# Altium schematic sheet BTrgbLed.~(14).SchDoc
size A4
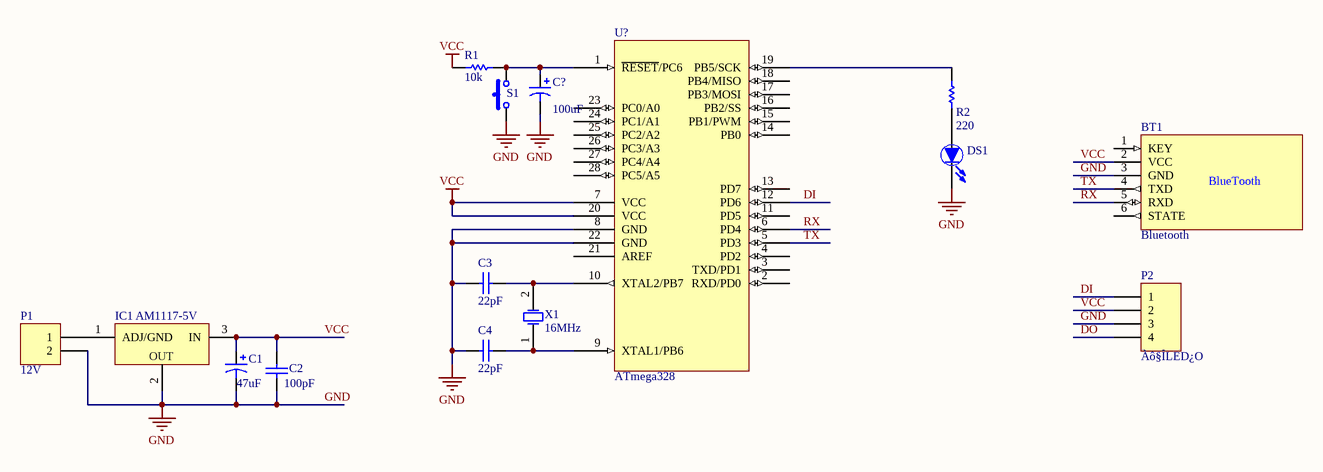
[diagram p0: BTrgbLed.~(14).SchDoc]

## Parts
BT1  Bluetooth  [Bluetooth]
C1  47uF  [RB7.6-15]
C2  value 100pF  [RAD-0.3]  (hidden comment: Cap)
C3  22pF  [C200]
C4  22pF  [C200]
C?  value 100uF  [RB7.6-15]  (hidden comment: Cap Pol1)
DS1  TX-LED  [LED-3mm_G]  (value not drawn)
IC1  AM1117-5V  [SOT-223]
P1  12V  [HDR1X2]
P2  Àô§ÎLED¿O  [HDR1X4]
R1  10k  [AXIAL-0.3]
R2  220  [AXIAL-0.3]
S1  SW-PB  [TACK6]  (value not drawn)
U?  ATmega328  [TEXTTOOL-28]
X1  16MHz  [XTAL4-8]

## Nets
GND: BT1.3(GND) C1.2 C2.2 C3.1 C4.1 C?.2 DS1.2(K) IC1.2(OUT) P1.2 P2.3 S1.1 U?.8(GND) U?.22(GND)
VCC: BT1.2(VCC) C1.1 C2.1 IC1.3(IN) P2.2 R1.1 U?.7(VCC) U?.20(VCC)
DI: P2.1 U?.12(PD6)
DO: P2.4
RX: BT1.5(RXD) U?.6(PD4)
TX: BT1.4(TXD) U?.5(PD3)
NetC3_2: C3.2 U?.10(XTAL2/PB7) X1.2(OSC2)
NetC4_2: C4.2 U?.9(XTAL1/PB6) X1.1(OSC1)
NetC?_1: C?.1 R1.2 S1.2 U?.1(~{RESET}/PC6)
NetDS1_1: DS1.1(A) R2.1
NetIC1_1: IC1.1(ADJ/GND) P1.1
NetR2_2: R2.2 U?.19(PB5/SCK)

Not connected (* = marked no-connect by the designer): BT1 1(KEY) 6(STATE); U? 2(RXD/PD0) 3(TXD/PD1) 4(PD2) 11(PD5) 13(PD7) 14(PB0) 15(PB1/PWM) 16(PB2/SS) 17(PB3/MOSI) 18(PB4/MISO) 21(AREF) 23(PC0/A0) 24(PC1/A1) 25(PC2/A2) 26(PC3/A3) 27(PC4/A4) 28(PC5/A5)

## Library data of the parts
C1 C? = Cap Pol1: Polarized Capacitor (Radial)
C2-C4 = Cap: Capacitor
DS1 = LED: Typical INFRARED GaAs LED
IC1 = AM1117
P1 = Header 2: Header, 2-Pin
P2 = Header 4: Header, 4-Pin
R1 R2 = Res: Resistor
S1 = SW-PB: Switch
U? = ATmega328: Arduino
X1 = XTAL: Crystal Oscillator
